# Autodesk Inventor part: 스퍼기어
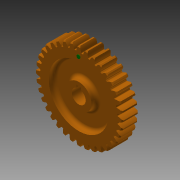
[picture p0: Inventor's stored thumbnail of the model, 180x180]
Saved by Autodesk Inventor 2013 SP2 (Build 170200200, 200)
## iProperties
Created: 2019-01
Part Number: 스퍼기어
Material: 알루미늄 6061
Document SubType Name: Modeling
Designer: mduedu
Density: 2.71 g/cm^3
Mass: 107.477 g
Surface Area: 168.408 cm^2
Volume: 39.6595 cm^3
Author: mduedu
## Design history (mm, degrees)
sketch "스케치1"
  geometry: C1 r 33.5 at (0, 0); C2 r 36 at (0, 0); C3 r 38 at (0, 0); 1 further point
  constraints: 3 centre point, 3 coincident
  dimensions: "d0" = 67 diameter of C1; "d2" = 72 diameter of C2; "d3" = 76 diameter of C3
extrude "돌출1" new body sketch "스케치1" distance "d4" = 14; taper "d5" = 0 deg
sketch "스케치2"
  geometry: L1 (0, 0)-(-38, 0); L2 (0, 0)-(0, 38); L3 (-0.57, 0)-(-0.57, 37.996); L4 (-1.57, 0)-(-1.57, 35.966); L5 (-2.07, 0)-(-2.07, 33.436); A1 r 38 centre (0, 0) between (-38, 0) and (0, 38) reference; A2 r 9.246 centre (7.162, 32.926) between (-0.57, 37.996) and (-2.07, 33.436); A3 r 9.246 centre (-7.162, 32.926) between (2.07, 33.436) and (0.57, 37.996); A4 r 33.5 centre (0, 0) between (2.07, 33.436) and (-2.07, 33.436); A5 r 38 centre (0, 0) between (0.57, 37.996) and (-0.57, 37.996); 2 further points
  constraints: 12 point on circle, 10 end point, 4 centre point, 3 parallel, 3 symmetric about line, 2 coincident, 1 horizontal, 1 perpendicular, 5 other
  dimensions: "d6" = 0.5 distance between parallel lines of L4 L5; "d8" = 1 distance between parallel lines of L3 L4; "d9" = 1.57 distance between parallel lines of L2 L4
extrude "돌출2" join sketch "스케치2" stored distance "d10" = 14; taper "d11" = 0 deg
chamfer "모따기1" distance "d12" = 1; stored, may be unused: second distance "d13" = 2, angle "d14" = 45 deg
fillet "모깎기1" dims "d15" = 0.5
sketch "스케치3"
  geometry: C1 r 11 at (0, 0); 1 further point
  constraints: 1 centre point, 1 coincident
  dimensions: "d19" = 22 diameter of C1
extrude "돌출3" join sketch "스케치3" distance "d20" = 6; taper "d21" = 0 deg
sketch "스케치4"
  geometry: C1 r 11 at (0, 0); C2 r 26 at (0, 0); 1 further point
  constraints: 2 centre point, 2 coincident
  dimensions: "d23" = 22 diameter of C1; "d24" = 52 diameter of C2
extrude "돌출4" cut sketch "스케치4" distance "d25" = 5; taper "d26" = 0 deg
fillet "모깎기3" dims "d27" = 3
node "작업 평면1"
sketch "스케치5" dims "d28" = 60
  geometry: C1 r 1.5 at (0, 30); 2 further points
  constraints: 2 vertical alignment, 1 centre point, 1 coincident, 2 other
  dimensions: "d29" = 3 diameter of C1
extrude "돌출5" join sketch "스케치5" distance "d30" = 0.5; taper "d31" = 0 deg
sketch "스케치6"
  geometry: L1 (-2, 5.657)-(2, 5.657); L2 (2, 5.657)-(2, 7.8); L3 (2, 7.8)-(-2, 7.8); L4 (-2, 7.8)-(-2, 5.657); A1 r 6 centre (0, 0) between (-2, 5.657) and (2, 5.657); 1 further point
  constraints: 8 end point, 2 parallel, 2 point on circle, 1 centre point, 1 coincident, 1 horizontal, 1 perpendicular
  dimensions: "d32" = 13.8 dimension on A1 L3; "d34" = 4 distance of L2.end L3.end; "d35" = 12 diameter of A1
extrude "돌출6" cut sketch "스케치6" stored distance "d36" = 0.5; taper "d37" = 0 deg
chamfer "모따기2" distance "d38" = 1; stored, may be unused: second distance "d39" = 2, angle "d40" = 45 deg
node "솔리드1"
pattern_circular "원형 패턴1" dims "d17" = 360 deg
mirror "대칭1"
